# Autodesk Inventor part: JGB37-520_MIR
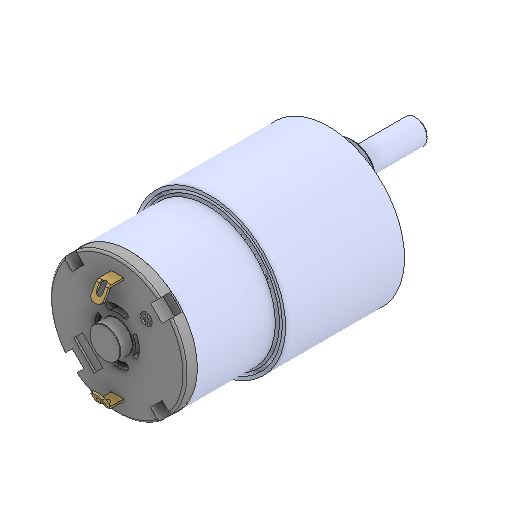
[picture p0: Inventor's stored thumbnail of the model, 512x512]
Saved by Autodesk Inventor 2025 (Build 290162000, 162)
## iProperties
Created: 2017-03
Part Number: JGB37-520_MIR
Material: Generico
Description: STEP AP214
Document SubType Name: Modeling
Designer: R5800u
Density: 1 g/cm^3
Appearance: Default
Title: JGB37-520.STEP
Sending System: SolidWorks 2017
Preprocessor: SwSTEP 2.0
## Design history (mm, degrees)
derived "JGB37-520.ipt"
feature "Solido1::JGB37-520.ipt"
feature "Solido2::JGB37-520.ipt"
feature "Solido3::JGB37-520.ipt"
feature "Solido4::JGB37-520.ipt"
feature "Solido5::JGB37-520.ipt"
feature "Solido6::JGB37-520.ipt"
feature "Solido7::JGB37-520.ipt"
feature "Solido8::JGB37-520.ipt"
feature "Solido9::JGB37-520.ipt"
feature "Solido10::JGB37-520.ipt"
feature "Solido11::JGB37-520.ipt"
tag "Lavorazione contrassegno1"
node "Solido1"
node "Solido2"
node "Solido3"
node "Solido4"
node "Solido5"
node "Solido6"
node "Solido7"
node "Solido8"
node "Solido9"
node "Solido10"
node "Solido11"
